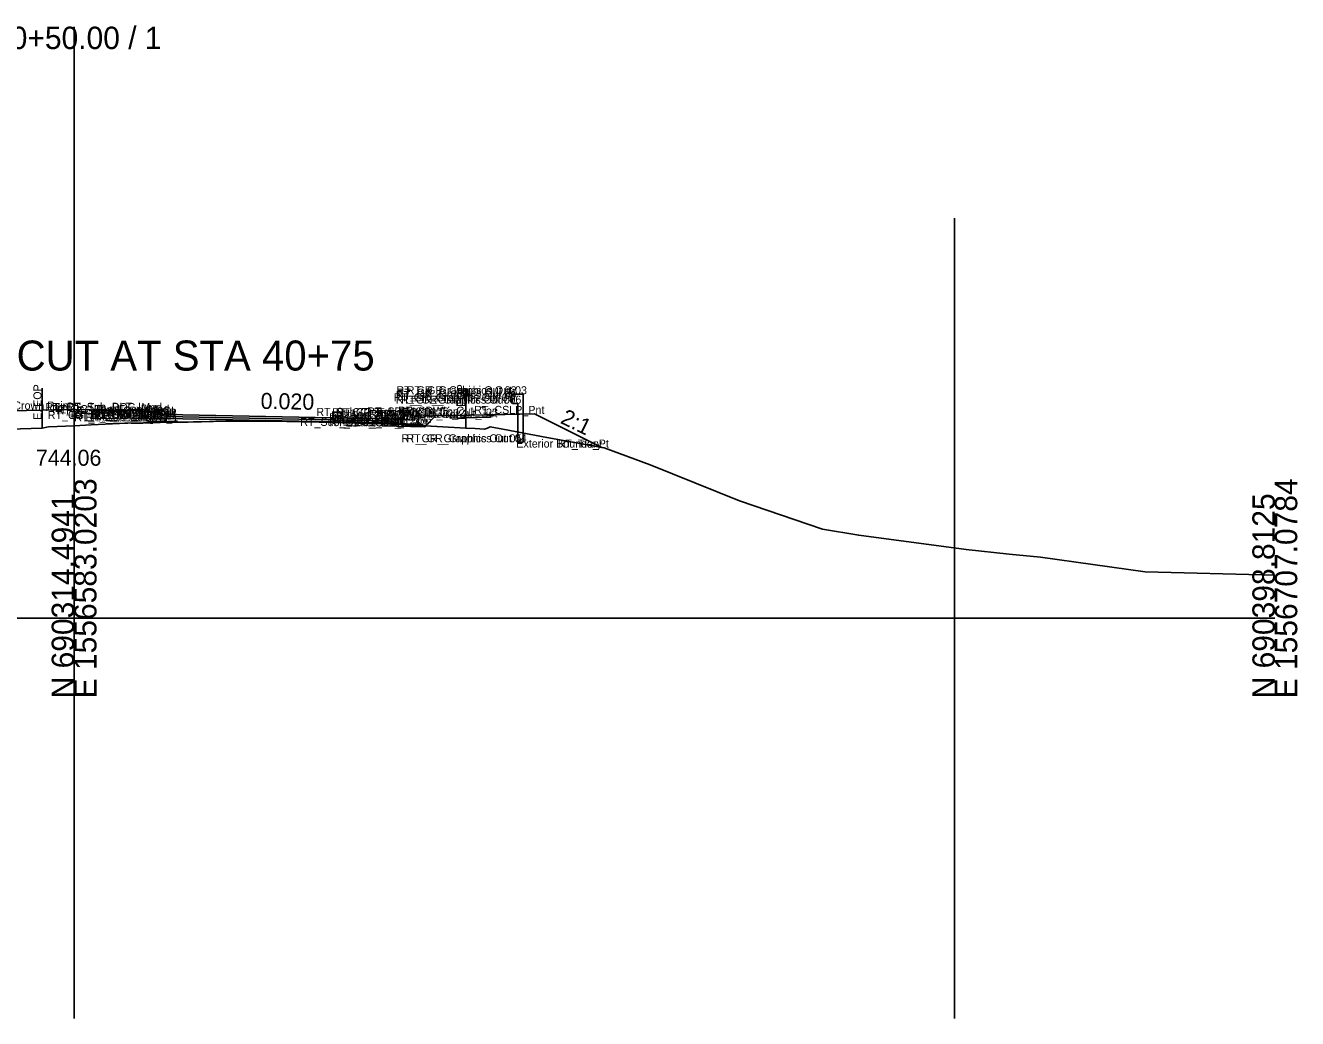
# Model space of a CAD drawing. Extents: x -26 to 6300, y -50 to 9577.
# Drawn here: x 143.9 to 302.8, y 6950 to 7074.1 of the extents above; entities that cross this region are included whole.
import ezdxf

# ---------------------------------------------------------------- set-up
doc = ezdxf.new("R2010")
doc.units = 0
for name, color, linetype in [('Default', 7, 'Continuous'), ('Exist CMT Pavement', 7, 'Continuous'), ('Exist Cross Section Cell', 7, 'Continuous'), ('Exist XS Center Line Elevation Label', 7, 'Continuous'), ('Exist XS Ground Line', 7, 'Continuous'), ('Prop CMT Conc Surface', 7, 'Continuous'), ('Prop CMT Concrete Structures', 7, 'Continuous'), ('Prop CMT Guardrail Graphics', 7, 'Continuous'), ('Prop CMT Pvmt Course 1', 7, 'Continuous'), ('Prop CMT Pvmt Course 1 CG', 7, 'Continuous'), ('Prop CMT Pvmt Course 2', 7, 'Continuous'), ('Prop CMT Pvmt Course 3', 7, 'Continuous'), ('Prop CMT Pvmt Surface', 7, 'Continuous'), ('Prop CMT Slope Grass', 7, 'Continuous'), ('Prop CMT Subgrade Earthwork', 7, 'Continuous'), ('Prop XS Earthwork Shape', 7, 'Continuous'), ('Prop XS Label Text', 7, 'Continuous'), ('Prop XS SE Text', 7, 'Continuous'), ('Prop XS Side Slope Text', 7, 'Continuous'), ('Prop XSC Text', 7, 'Continuous'), ('Scratch_Level_2', 7, 'Continuous'), ('Scratch_Level_9', 7, 'Continuous')]:
    doc.layers.add(name, color=color, linetype=linetype)

msp = doc.modelspace()

# ---------------------------------------------------------------- linework, layer by layer
at = {"layer": 'Exist CMT Pavement'}
msp.add_lwpolyline([(164.25, 7024.52), (165.92, 7024.56), (168.97, 7024.62), (170.42, 7024.62), (171.88, 7024.62), (173.08, 7024.63), (174.77, 7024.63), (175.24, 7024.61), (176.57, 7024.59), (179.62, 7024.53), (182.67, 7024.46), (185.71, 7024.38), (188.5, 7024.31)], dxfattribs=at)
at = {"layer": 'Exist Cross Section Cell'}
for p, q in [((150, 7000), (150, 7073.91)), ((0, 7000), (150, 7000)), ((150, 7000), (300, 7000))]:
    msp.add_line(p, q, dxfattribs=at)
at = {"layer": 'Exist XS Ground Line'}
msp.add_lwpolyline([(141.93, 7023.62), (146.02, 7023.77), (146.81, 7023.9), (150, 7024.05), (152.13, 7024.15), (156.55, 7024.39), (162.86, 7024.49), (168.97, 7024.62), (171.88, 7024.62), (174.29, 7024.64), (175.24, 7024.61), (176.57, 7024.59), (182.67, 7024.46), (188.74, 7024.31), (190.87, 7024.2), (193.07, 7024.09), (196.06, 7023.92), (198.94, 7023.76), (200.1, 7023.71), (201.26, 7023.64), (201.63, 7023.76), (201.97, 7023.9), (203.55, 7023.63), (209.07, 7022.59), (216.21, 7021.28), (221.98, 7019.16), (233.14, 7014.67), (243.5, 7011.13), (248.02, 7010.37), (261.44, 7008.6), (266.81, 7008.01), (270.71, 7007.64), (283.8, 7005.79), (300, 7005.4)], dxfattribs=at)
at = {"layer": 'Prop CMT Conc Surface'}
for points in [[(161.5, 7025.45), (160.75, 7025.47), (160.75, 7025.63), (159.99, 7025.88)], [(190.5, 7024.87), (192.5, 7024.75)], [(192.5, 7024.75), (192.5, 7025.25), (193, 7025.25)], [(197, 7025.34), (202, 7025.44)]]:
    msp.add_lwpolyline(points, dxfattribs=at)
at = {"layer": 'Prop CMT Concrete Structures'}
for points in [[(161.5, 7025.45), (160.75, 7025.47), (160.75, 7025.63), (159.99, 7025.88)], [(159.99, 7025.88), (159.99, 7024.9)], [(159.99, 7024.9), (161.5, 7024.87)], [(161.5, 7024.87), (161.5, 7025.45)], [(190.5, 7024.87), (192.5, 7024.75), (192.5, 7025.25), (193, 7025.25)], [(193, 7025.25), (193, 7024.24), (190.5, 7024.29)], [(190.5, 7024.29), (190.5, 7024.87)], [(202, 7025.44), (197, 7025.34)], [(197, 7025.34), (197, 7025.01)], [(197, 7025.01), (202, 7025.11)], [(202, 7025.11), (202, 7025.44)]]:
    msp.add_lwpolyline(points, dxfattribs=at)
at = {"layer": 'Prop CMT Guardrail Graphics'}
for points in [[(206.1, 7027.99), (204.77, 7027.99), (204.5, 7027.69)], [(204.5, 7027.69), (204.77, 7027.4)], [(204.77, 7027.4), (204.5, 7027.11)], [(206.1, 7021.99), (206.1, 7027.99)], [(204.5, 7027.11), (204.77, 7026.82), (205.44, 7026.82)], [(205.44, 7026.82), (205.44, 7021.99)], [(205.44, 7021.99), (206.1, 7021.99)]]:
    msp.add_lwpolyline(points, dxfattribs=at)
at = {"layer": 'Prop CMT Pvmt Course 1'}
for points in [[(161.5, 7025.45), (190.5, 7024.87)], [(161.5, 7025.2), (161.5, 7025.45)], [(190.5, 7024.62), (161.5, 7025.2)], [(161.5, 7025.2), (161.5, 7025.2), (161.5, 7025.2)], [(188.5, 7024.91), (188.5, 7024.66)], [(190.5, 7024.87), (190.5, 7024.62)]]:
    msp.add_lwpolyline(points, dxfattribs=at)
at = {"layer": 'Prop CMT Pvmt Course 1 CG'}
for points in [[(161.5, 7024.87), (159.49, 7024.91), (159.2, 7024.62)], [(159.24, 7024.62), (161.5, 7024.58)], [(161.5, 7024.62), (161.5, 7024.87)], [(190.5, 7024.29), (193.5, 7024.23), (193.8, 7023.93)], [(190.5, 7024.04), (190.5, 7024.29)], [(193.8, 7023.93), (188.5, 7024.04)]]:
    msp.add_lwpolyline(points, dxfattribs=at)
at = {"layer": 'Prop CMT Pvmt Course 2'}
for points in [[(161.5, 7024.95), (161.5, 7025.2)], [(161.5, 7025.2), (190.5, 7024.62)], [(190.5, 7024.37), (161.5, 7024.95)], [(188.5, 7024.66), (188.5, 7024.41)], [(190.5, 7024.62), (190.5, 7024.37)]]:
    msp.add_lwpolyline(points, dxfattribs=at)
at = {"layer": 'Prop CMT Pvmt Course 3'}
for points in [[(161.5, 7024.95), (190.5, 7024.37)], [(161.5, 7024.58), (161.5, 7024.95)], [(164.25, 7024.52), (161.5, 7024.58)], [(188.5, 7024.41), (188.5, 7024.04)], [(190.5, 7024.37), (190.5, 7024)]]:
    msp.add_lwpolyline(points, dxfattribs=at)
at = {"layer": 'Prop CMT Pvmt Surface'}
msp.add_lwpolyline([(161.5, 7025.45), (190.5, 7024.87)], dxfattribs=at)
at = {"layer": 'Prop CMT Slope Grass'}
for points in [[(140.01, 7025.88), (150, 7026.08)], [(159.99, 7025.88), (150, 7026.08)], [(193, 7025.25), (207.5, 7025.54)], [(207.5, 7025.54), (215.92, 7021.33)]]:
    msp.add_lwpolyline(points, dxfattribs=at)
at = {"layer": 'Prop CMT Subgrade Earthwork'}
for p, q in [((188.5, 7024.04), (188.5, 7024.31)), ((193.8, 7023.93), (195.16, 7025.3))]:
    msp.add_line(p, q, dxfattribs=at)
for points in [[(157.9, 7025.93), (159.2, 7024.62)], [(159.2, 7024.62), (161.5, 7024.58)], [(161.5, 7024.58), (161.5, 7024.58)], [(161.5, 7024.58), (164.25, 7024.52)], [(188.5, 7024.04), (193.8, 7023.93)]]:
    msp.add_lwpolyline(points, dxfattribs=at)
at = {"layer": 'Prop XS Earthwork Shape'}
msp.add_lwpolyline([(141.93, 7023.62), (146.02, 7023.77), (146.81, 7023.9), (150, 7024.05), (150, 7026.08), (142.1, 7025.93)], dxfattribs=at)
for points in [[(161.5, 7024.58), (164.25, 7024.52), (162.86, 7024.49), (156.55, 7024.39), (152.13, 7024.15), (150, 7024.05), (150, 7026.08), (157.9, 7025.93), (159.2, 7024.62)], [(173.08, 7024.63), (174.77, 7024.63), (174.29, 7024.64)], [(188.5, 7024.04), (188.5, 7024.31), (188.74, 7024.31), (190.87, 7024.2), (193.07, 7024.09), (193.91, 7024.04), (193.8, 7023.93)], [(209.07, 7022.59), (215.92, 7021.33), (207.5, 7025.54), (202, 7025.44), (202, 7025.11), (197, 7025.01), (197, 7025.34), (195.16, 7025.3), (193.91, 7024.04), (196.06, 7023.92), (198.94, 7023.76), (200.1, 7023.71), (201.26, 7023.64), (201.63, 7023.76), (201.97, 7023.9), (203.55, 7023.63)]]:
    msp.add_lwpolyline(points, close=True, dxfattribs=at)
at = {"layer": 'Prop XS Label Text'}
for p, q in [((146.02, 7028.77), (146.02, 7023.77)), ((198.94, 7028.76), (198.94, 7023.76))]:
    msp.add_line(p, q, dxfattribs=at)
at = {"layer": 'Scratch_Level_2'}
msp.add_line((150, 7050), (150, 6950), dxfattribs=at)
at = {"layer": 'Scratch_Level_9'}
msp.add_line((260, 7050), (260, 6950), dxfattribs=at)

# ---------------------------------------------------------------- texts
at = {"layer": 'Default'}
for s, p in [('RT_GR_Graphics Out 02', (190.26, 7027.99)), ('RT_GR_Graphics Out 03', (191.56, 7027.99)), ('RT_GR_Graphics Out 08', (189.92, 7027.11)), ('RT_GR_Graphics Out 07', (190.17, 7026.82)), ('RT_GR_Graphics Out 09', (190.2, 7027.4)), ('RT_GR_Graphics Out 01', (190.28, 7027.69)), ('RT_GR_Graphics Out 06', (190.86, 7026.82)), ('MD_Crown Point', (139.58, 7026.08)), ('RT_CG_Top_BOC_Med', (146.43, 7025.88)), ('RT_CG_Bot_BOC_Med', (146.71, 7024.9)), ('RT_CG_Top_Face_Med', (147.25, 7025.63)), ('RT_CG_Top_Gut_Med', (147.8, 7025.47)), ('RT_Sub_DLT_In', (149.07, 7025.93)), ('RT_CG1_Shelf_In', (149.57, 7024.91)), ('RT_CG_Bot_IE_Med', (149.98, 7024.87)), ('RT_PV2_OEEOP', (152.17, 7025.2)), ('RT_PV3_OEEOP', (152.17, 7024.95)), ('RT_PV2_IEEOP', (152.93, 7025.2)), ('RT_PV2_PGL', (154.15, 7025.2)), ('RT_PV1_PGL', (154.38, 7025.45)), ('RT_Sub_Trench_Out_DLT', (180.26, 7025.29)), ('RT_PV1_OEOT', (182.11, 7024.87)), ('RT_CG_Top_Face', (182.22, 7025.25)), ('RT_CG_Top_BOC', (182.69, 7025.25)), ('RT_CG_Top_Gut', (182.75, 7024.75)), ('RT_SDWK_In_Top', (186.62, 7025.34)), ('RT_SDWK_In_Bot', (186.87, 7025.01)), ('RT_SDWK_Out_Top', (190.46, 7025.44)), ('RT_SDWK_Out_Bot', (190.71, 7025.11)), ('RT_CSLP_Pnt', (199.98, 7025.54)), ('RT_Sub_IEOT_CG_1', (150.01, 7024.62)), ('RT_Sub_IEOP', (151.42, 7024.67)), ('RT_Sub_OEEOP', (152.21, 7024.58)), ('RT_Sub_IEEOP', (152.97, 7024.58)), ('RT_Sub_PGL', (154.19, 7024.58)), ('RT_Sub_OEOT_CG_1', (178.25, 7024.04)), ('RT_PV2_OEOT', (181.87, 7024.62)), ('RT_PV3_OEOT', (181.87, 7024.37)), ('RT_Sub_OEOT', (181.92, 7024)), ('RT_CG_Bot_IE', (182.22, 7024.29)), ('RT_CG1_Shelf_Out', (182.36, 7024.23)), ('RT_CG_Bot_BOC', (182.97, 7024.24)), ('RT_Sub_OEOP', (185.17, 7023.97)), ('RT_GR_Graphics Out 05', (190.88, 7021.99)), ('RT_GR_Graphics Out 04', (191.52, 7021.99)), ('Exterior Boundary', (205.24, 7021.33)), ('RT_Tie_Pt', (210.41, 7021.33))]:
    msp.add_text(s, height=1, dxfattribs=at).set_placement(p)
at = {"layer": 'Exist Cross Section Cell'}
msp.add_text('40+50.00 / 1', height=2.8, dxfattribs=at).set_placement((140, 7071.11))
for s, p in [('E 1556583.0203', (152.8, 6990)), ('E 1556707.0784', (302.8, 6990)), ('N 690314.4941', (150, 6990)), ('N 690398.8125', (300, 6990))]:
    msp.add_text(s, height=2.8, rotation=90, dxfattribs=at).set_placement(p)
at = {"layer": 'Exist XS Center Line Elevation Label'}
msp.add_text('744.06', height=2, dxfattribs=at).set_placement((145.23, 7019.06))
at = {"layer": 'Prop XS Label Text'}
for p in [(145.92, 7024.78), (198.84, 7024.78)]:
    msp.add_text('E. EOP', height=1, rotation=90, dxfattribs=at).set_placement(p)
at = {"layer": 'Prop XS SE Text'}
msp.add_text('0.020', height=2, rotation=358.8542, dxfattribs=at).set_placement((173.29, 7026.17))
at = {"layer": 'Prop XS Side Slope Text'}
msp.add_text('2:1', height=2, rotation=333.9281, dxfattribs=at).set_placement((210.63, 7024.44))
at = {"layer": 'Prop XSC Text'}
msp.add_text('END UNDERCUT AT STA 40+75', height=3.75, dxfattribs=at).set_placement((113.01, 7030.95))

doc.saveas('drawing.dxf')
